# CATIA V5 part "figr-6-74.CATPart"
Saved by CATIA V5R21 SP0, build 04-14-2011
Part number: Part2
Bounding box of the stored display mesh (mm): x -37.886 to 37.886, y -61.415 to 61.415, z 0 to 29
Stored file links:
  D:\CATIA V5R21 E-RESOURCES\CATIA-V5R21\catia-v5r21-prt\c06-catia-v5r21-prt\c06-catia-v5r21-figr-6-74.CATPart
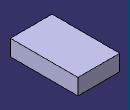
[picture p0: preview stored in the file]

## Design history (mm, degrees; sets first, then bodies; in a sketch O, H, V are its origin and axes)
Body1 (main body)
  Sketch1 on xy-plane, origin (0, 0, 0), H (1, 0, 0), V (0, 1, 0)
    line L1 (37.8862, 61.4155) -> (37.8862, -61.4155)
    line L2 (37.8862, -61.4155) -> (-37.8862, -61.4155)
    line L3 (-37.8862, -61.4155) -> (-37.8862, 61.4155)
    line L4 (-37.8862, 61.4155) -> (37.8862, 61.4155)
    vertical: L1 V, L3 V
    horizontal: L2 H, L4 H
    equidistance: L1 L3 O, L2 L4 O
  Pad1: profile Sketch1, direction (0, 0, 1), length 29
